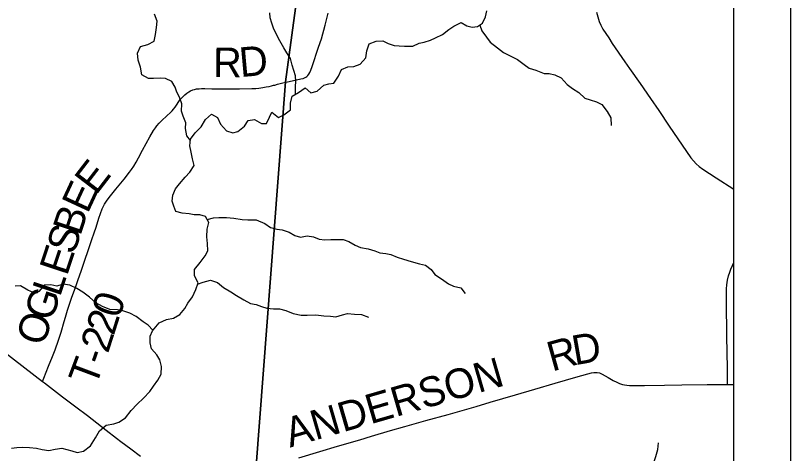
# Model space of a CAD drawing. Extents: x 0 to 34, y 0 to 22.
# Drawn here: x 7.686 to 9.17, y 15.496 to 16.336 of the extents above; entities that cross this region are included whole.
import ezdxf

# ---------------------------------------------------------------- set-up
doc = ezdxf.new("R2010")
doc.units = 0
for name, color, linetype in [('Default', 7, 'Continuous'), ('GM_X_County_Road', 7, 'Continuous'), ('GM_X_Minor_River', 7, 'Continuous'), ('GM_X_State_Route', 7, 'Continuous'), ('GM_X_Township_Road', 7, 'Continuous'), ('GM_X_Township_Road_Text', 7, 'Continuous'), ('SH_Cut_Line', 7, 'Continuous'), ('SH_Data', 7, 'Continuous')]:
    doc.layers.add(name, color=color, linetype=linetype)

msp = doc.modelspace()

# ---------------------------------------------------------------- linework, layer by layer
at = {"layer": 'Default'}
msp.add_lwpolyline([(3.47, 19.2407), (3.2768, 17.1355), (3.2667, 16.919), (3.1974, 16.1596), (3.1343, 15.4291), (3.1796, 15.4266), (4.2078, 15.3826), (4.2393, 15.3805), (4.819, 15.349), (5.5157, 15.319), (7.9465, 15.1727), (8.1234, 15.1688), (8.137, 15.3372), (8.146, 15.4642), (8.2031, 16.209), (8.2895, 16.85), (8.3286, 17.3076), (8.3307, 17.3314), (8.3334, 17.361), (8.3935, 18.0719)], dxfattribs=at)
msp.add_lwpolyline([(8.4279, 13.6252), (9.0621, 13.6252), (9.0621, 18.0279), (9.0619, 18.0279), (8.9638, 18.036), (8.3935, 18.0719), (8.3334, 17.361), (8.3307, 17.3314), (8.3286, 17.3076), (8.2895, 16.85), (8.2031, 16.209), (8.146, 15.4642), (8.137, 15.3372), (8.1234, 15.1688), (8.3761, 15.1587), (8.4023, 15.1576), (8.4024, 15.1386)], close=True, dxfattribs=at)
at = {"layer": 'GM_X_County_Road'}
msp.add_lwpolyline([(8.799, 16.3425), (8.8012, 16.3335), (8.8041, 16.3247), (8.807, 16.318), (8.8111, 16.3104), (8.8221, 16.2932), (8.829, 16.2829), (8.8533, 16.2476), (8.8622, 16.2349), (8.8823, 16.2057), (8.9019, 16.177), (8.9179, 16.154), (8.9382, 16.1242), (8.9795, 16.0637), (8.9845, 16.0574), (8.9896, 16.0517), (8.9955, 16.0468), (9.0024, 16.0417), (9.028, 16.0253), (9.0621, 16.0036)], dxfattribs=at)
at = {"layer": 'GM_X_Minor_River'}
for points in [[(8.0206, 16.0969), (8.0138, 16.1058), (8.0111, 16.1195), (8.0117, 16.1308), (8.007, 16.1435), (8.0038, 16.153), (8.0041, 16.1667), (7.9998, 16.1796), (7.9947, 16.1896), (7.9915, 16.1992), (7.9852, 16.2095), (7.9732, 16.2158), (7.9634, 16.2164), (7.9501, 16.2155), (7.9403, 16.2153), (7.9279, 16.2228), (7.9252, 16.2373), (7.9205, 16.2506), (7.9193, 16.2643), (7.9252, 16.2767), (7.9394, 16.281), (7.9512, 16.2868), (7.9541, 16.2997), (7.9555, 16.3133), (7.9573, 16.3254), (7.9519, 16.3388)], [(8.0519, 15.9119), (8.0526, 15.9267), (8.0562, 15.9395), (8.0496, 15.9507), (8.0387, 15.9539), (8.0281, 15.9541), (8.0183, 15.9558), (8.0051, 15.9572), (7.9926, 15.9605), (7.9887, 15.9708), (7.9858, 15.9804), (7.9872, 15.9921), (7.992, 16.0038), (7.9998, 16.0135), (8.0107, 16.0262), (8.0199, 16.0358), (8.0278, 16.0486), (8.025, 16.0612), (8.0222, 16.0741), (8.0195, 16.0863), (8.0209, 16.0992), (8.0298, 16.1111), (8.0414, 16.1227), (8.0497, 16.1369), (8.0609, 16.1469), (8.0725, 16.141), (8.0783, 16.128), (8.0898, 16.1153), (8.1018, 16.1112), (8.1113, 16.1141), (8.1244, 16.1244), (8.1315, 16.1349), (8.1436, 16.137), (8.1567, 16.1291), (8.1662, 16.1293), (8.1725, 16.1413), (8.1769, 16.1511), (8.1895, 16.141), (8.1999, 16.1461), (8.2126, 16.1557), (8.2125, 16.1682), (8.2154, 16.1814), (8.228, 16.1884), (8.2403, 16.1976), (8.2515, 16.1883), (8.2637, 16.1915), (8.2761, 16.2026), (8.286, 16.2055), (8.2958, 16.2064), (8.3045, 16.2203), (8.3104, 16.2331), (8.3222, 16.2378), (8.3336, 16.2383), (8.3458, 16.243), (8.3567, 16.2549), (8.3585, 16.2685), (8.3633, 16.2817), (8.3763, 16.2868), (8.3892, 16.2876), (8.3993, 16.2825), (8.411, 16.2789), (8.4208, 16.2783), (8.431, 16.2777), (8.4466, 16.2778), (8.4588, 16.2832), (8.4683, 16.2853), (8.4805, 16.2889), (8.4904, 16.2932), (8.5035, 16.3002), (8.5158, 16.3098), (8.5254, 16.3161), (8.5395, 16.3226), (8.55, 16.3167), (8.5606, 16.3138), (8.5708, 16.3152), (8.5804, 16.3218), (8.586, 16.3338), (8.5889, 16.3455)], [(8.2222, 16.1852), (8.2218, 16.1999), (8.2228, 16.2098), (8.2222, 16.2208), (8.2191, 16.2311), (8.2158, 16.241), (8.2123, 16.254), (8.2057, 16.2647), (8.1995, 16.2743), (8.1918, 16.2878), (8.1856, 16.2996), (8.1802, 16.3123), (8.177, 16.3218), (8.1738, 16.3321), (8.1728, 16.3416)], [(8.575, 16.3181), (8.579, 16.307), (8.5878, 16.2951), (8.5952, 16.2851), (8.609, 16.2742), (8.6206, 16.2652), (8.6348, 16.2581), (8.6472, 16.2518), (8.6603, 16.2425), (8.67, 16.2351), (8.6824, 16.2318), (8.6982, 16.2254), (8.708, 16.2248), (8.7186, 16.2223), (8.7313, 16.2168), (8.7424, 16.2037), (8.7529, 16.1962), (8.7648, 16.1884), (8.7767, 16.1776), (8.7865, 16.1743), (8.799, 16.171), (8.8091, 16.1659), (8.8194, 16.1524), (8.826, 16.1398), (8.8268, 16.1257)], [(8.0528, 15.9453), (8.0647, 15.9481), (8.0754, 15.949), (8.0898, 15.9487), (8.1041, 15.9477), (8.12, 15.9451), (8.131, 15.9445), (8.1469, 15.9442), (8.163, 15.9374), (8.1742, 15.93), (8.1863, 15.9267), (8.1965, 15.925), (8.21, 15.9206), (8.2205, 15.9147), (8.2314, 15.9114), (8.2444, 15.9138), (8.2565, 15.912), (8.2673, 15.9073), (8.2783, 15.9063), (8.2897, 15.9068), (8.2995, 15.907), (8.3132, 15.9068), (8.3245, 15.9031), (8.3364, 15.8957), (8.3466, 15.8913), (8.3613, 15.8891), (8.3741, 15.8851), (8.3839, 15.8815), (8.3952, 15.8797), (8.405, 15.878), (8.417, 15.8732), (8.4291, 15.8688), (8.4438, 15.8647), (8.4596, 15.8602), (8.4713, 15.8573), (8.4817, 15.8492), (8.4891, 15.8395), (8.5018, 15.8313), (8.5152, 15.8219), (8.525, 15.8172), (8.539, 15.8143), (8.5474, 15.8031)], [(7.678, 15.5069), (7.6882, 15.5079), (7.6988, 15.5084), (7.7125, 15.5078), (7.7261, 15.5068), (7.737, 15.5039), (7.7495, 15.5021), (7.7613, 15.5045), (7.7742, 15.5066), (7.7938, 15.5016), (7.804, 15.4984), (7.8158, 15.5008), (7.8296, 15.5108), (7.8386, 15.5265), (7.8465, 15.5397), (7.8592, 15.5508), (7.874, 15.5535), (7.8836, 15.5567), (7.8962, 15.5648), (7.9075, 15.5787), (7.9184, 15.591), (7.9307, 15.6025), (7.9427, 15.6155), (7.9498, 15.6256), (7.958, 15.6368), (7.9646, 15.6488), (7.9653, 15.6633), (7.9622, 15.6762), (7.9563, 15.6858), (7.9459, 15.697), (7.9435, 15.7084), (7.9438, 15.7217), (7.9482, 15.7319), (7.961, 15.7472), (7.9751, 15.7533), (7.9881, 15.7561), (8.0007, 15.7627), (8.01, 15.7743), (8.0159, 15.7848), (8.0245, 15.7968), (8.0312, 15.8107), (8.0353, 15.8239), (8.0287, 15.8369), (8.0286, 15.8494), (8.0391, 15.8629), (8.0488, 15.8752), (8.054, 15.8853), (8.0535, 15.8994), (8.0519, 15.9119)], [(8.0345, 15.8214), (8.0452, 15.8252), (8.0593, 15.8291), (8.0728, 15.8246), (8.084, 15.8149), (8.0982, 15.8063), (8.1087, 15.7996), (8.1229, 15.7914), (8.1356, 15.7839), (8.147, 15.7822), (8.1571, 15.7782), (8.1669, 15.7753), (8.1801, 15.7739), (8.1915, 15.7737), (8.2035, 15.7705), (8.2174, 15.7649), (8.2329, 15.7619), (8.2447, 15.7617), (8.2613, 15.7625), (8.2761, 15.7607), (8.2889, 15.76), (8.2991, 15.7583), (8.3121, 15.7622), (8.322, 15.7647), (8.3352, 15.7633), (8.3485, 15.763), (8.362, 15.7578)], [(7.9488, 15.7326), (7.94, 15.7423), (7.93, 15.7489), (7.9169, 15.7594), (7.9045, 15.7657), (7.891, 15.7698), (7.8812, 15.7719), (7.8664, 15.7726), (7.8525, 15.7785), (7.8398, 15.7856), (7.8271, 15.7965), (7.8148, 15.8058), (7.8032, 15.8125), (7.7897, 15.8192), (7.7769, 15.821), (7.765, 15.8171), (7.7533, 15.8196), (7.7405, 15.8194), (7.73, 15.8068), (7.7205, 15.8043), (7.7092, 15.8094), (7.6953, 15.8177), (7.6847, 15.8175)], [(9.0487, 15.3175), (9.0402, 15.3195), (9.026, 15.3282), (9.0141, 15.339), (9.0072, 15.3532), (9.001, 15.3632), (8.9876, 15.3744), (8.9767, 15.3803), (8.9621, 15.3859), (8.9456, 15.3954), (8.9345, 15.4077), (8.9294, 15.4211), (8.9243, 15.4307), (8.923, 15.4402), (8.9188, 15.4547), (8.9133, 15.4677), (8.9095, 15.4811), (8.9123, 15.4909), (8.916, 15.5041), (8.9178, 15.5169)]]:
    msp.add_lwpolyline(points, dxfattribs=at)
at = {"layer": 'GM_X_State_Route'}
msp.add_lwpolyline([(7.6637, 15.6916), (7.7375, 15.6347), (7.7414, 15.6317), (7.7759, 15.6052), (7.8011, 15.586), (7.8233, 15.569), (7.8592, 15.5413), (7.8789, 15.5261), (7.8873, 15.5197), (7.9066, 15.5052), (7.925, 15.4915)], dxfattribs=at)
at = {"layer": 'GM_X_Township_Road'}
msp.add_line((9.0499, 15.6289), (9.0621, 15.629), dxfattribs=at)
for points in [[(8.2043, 16.2086), (8.2323, 16.2146), (8.2365, 16.2156), (8.2393, 16.2166), (8.242, 16.218), (8.2439, 16.2194), (8.246, 16.2214), (8.2479, 16.2237), (8.2496, 16.2268), (8.2516, 16.2313), (8.2543, 16.2388), (8.2663, 16.2759), (8.2716, 16.2919), (8.2787, 16.3175), (8.2846, 16.3405)], [(7.7375, 15.6347), (7.7399, 15.6407), (7.7491, 15.6638), (7.7563, 15.6821), (7.7615, 15.6954), (7.768, 15.7138), (7.7728, 15.7292), (7.7786, 15.7495), (7.7811, 15.7576), (7.7852, 15.771), (7.7886, 15.7808), (7.7932, 15.7942), (7.7957, 15.8011), (7.8007, 15.8148), (7.8058, 15.8299), (7.8115, 15.8463), (7.8317, 15.9068), (7.8362, 15.9196), (7.8401, 15.9307), (7.8454, 15.948), (7.8483, 15.9568), (7.8518, 15.9655), (7.8536, 15.9695), (7.8563, 15.9745), (7.8601, 15.9803), (7.8653, 15.9873), (7.878, 16.0034), (7.8935, 16.0228), (7.9039, 16.0359), (7.9076, 16.0409), (7.9121, 16.0476), (7.9167, 16.0548), (7.9213, 16.0636), (7.9288, 16.0778), (7.9358, 16.0909), (7.9431, 16.1039), (7.9501, 16.1157), (7.9536, 16.1209), (7.9566, 16.1249), (7.9607, 16.1297), (7.9669, 16.1359), (7.9832, 16.1511), (7.9858, 16.1538), (7.9883, 16.1564), (7.9914, 16.1603), (7.9941, 16.1643), (7.9984, 16.1712), (8.0014, 16.1752), (8.0056, 16.18), (8.0101, 16.1844), (8.014, 16.1876), (8.0176, 16.1901), (8.021, 16.1919), (8.0251, 16.1936), (8.0288, 16.1946), (8.0327, 16.1954), (8.0372, 16.1958), (8.0422, 16.1961), (8.0485, 16.1961), (8.0615, 16.1957), (8.077, 16.1955), (8.0924, 16.1955), (8.1145, 16.1957), (8.1385, 16.1961), (8.1459, 16.1965), (8.152, 16.1971), (8.1593, 16.198), (8.166, 16.1993), (8.1714, 16.2004), (8.1761, 16.2015), (8.1802, 16.2025), (8.1825, 16.203), (8.1876, 16.2044), (8.1979, 16.2071), (8.2033, 16.2084), (8.2043, 16.2086)], [(9.0499, 15.6289), (9.0495, 15.6551), (9.0489, 15.6954), (9.0487, 15.7166), (9.0484, 15.7377), (9.0479, 15.7712), (9.0475, 15.8053), (9.0478, 15.8122), (9.0486, 15.8201), (9.05, 15.8286), (9.0519, 15.837), (9.0539, 15.8442), (9.056, 15.8499), (9.059, 15.8567), (9.0621, 15.8629)], [(8.2283, 15.4881), (8.2688, 15.5002), (8.3028, 15.5102), (8.3451, 15.5228), (8.3678, 15.5294), (8.4041, 15.5402), (8.4316, 15.548), (8.4716, 15.5596), (8.5147, 15.5714), (8.5679, 15.5868), (8.5953, 15.5948), (8.6436, 15.609), (8.6806, 15.6198), (8.7194, 15.6311), (8.7593, 15.6428), (8.782, 15.6493), (8.7894, 15.6512), (8.7938, 15.6518), (8.797, 15.652), (8.8001, 15.6518), (8.8045, 15.6508), (8.8097, 15.6484), (8.8211, 15.6419), (8.8308, 15.6363), (8.8374, 15.633), (8.8431, 15.6306), (8.8483, 15.6289), (8.8525, 15.6279), (8.8567, 15.6272), (8.8622, 15.6268), (8.8702, 15.6266), (8.8907, 15.6271), (8.9292, 15.6277), (8.9622, 15.6281), (9.0106, 15.6285), (9.0499, 15.6289)]]:
    msp.add_lwpolyline(points, dxfattribs=at)
at = {"layer": 'SH_Cut_Line'}
msp.add_lwpolyline([(2.9696, 13.6252), (9.0621, 13.6252), (9.0621, 20.4252), (3.5682, 20.4252), (3.5424, 20.1754), (3.5231, 19.8516), (3.5169, 19.7823), (3.5125, 19.7343), (3.5092, 19.6961), (3.5066, 19.6647), (3.4966, 19.5464), (3.4903, 19.4759), (3.4748, 19.2963), (3.47, 19.2407), (3.2768, 17.1355), (3.2667, 16.919), (3.1974, 16.1596), (3.1343, 15.4291), (3.0617, 14.6751), (3.0457, 14.4958), (3.0429, 14.4692)], close=True, dxfattribs=at)
at = {"layer": 'SH_Data'}
msp.add_line((9.1704, 20.5628), (9.1704, 13.5628), dxfattribs=at)

# ---------------------------------------------------------------- texts
at = {"layer": 'GM_X_Township_Road_Text'}
for s, height, rotation, p in [('R', 0.0568, 359.6097, (8.0641, 16.2182)), ('D', 0.0568, 5.1553, (8.1167, 16.2181)), ('E', 0.0568, 52.4701, (7.84, 15.9906)), ('E', 0.0568, 65.1563, (7.8238, 15.9548)), ('B', 0.0568, 71.4626, (7.8096, 15.9121)), ('S', 0.0568, 71.6199, (7.7975, 15.8758)), ('E', 0.0568, 71.6172, (7.7841, 15.8354)), ('L', 0.0568, 71.6192, (7.7707, 15.7951)), ('G', 0.0568, 71.618, (7.755, 15.7477)), ('0', 0.0568, 71.1775, (7.8841, 15.7538)), ('2', 0.0568, 72.4698, (7.8737, 15.7208)), ('O', 0.0568, 71.618, (7.7392, 15.7002)), ('2', 0.0568, 71.9823, (7.8627, 15.687)), ('D', 0.0568, 9.9363, (8.7571, 15.6655)), ('R', 0.0568, 15.6012, (8.7136, 15.6533)), ('T', 0.0568, 69.4259, (7.839, 15.6226)), ('-', 0.0568, 70.468, (7.8544, 15.6634)), ('ANDERSON', 0.05682, 16.1507, (8.2115, 15.5076))]:
    msp.add_text(s, height=height, rotation=rotation, dxfattribs=at).set_placement(p)

doc.saveas('drawing.dxf')
